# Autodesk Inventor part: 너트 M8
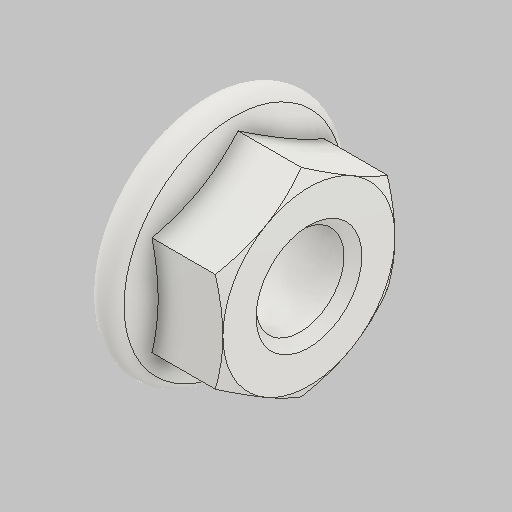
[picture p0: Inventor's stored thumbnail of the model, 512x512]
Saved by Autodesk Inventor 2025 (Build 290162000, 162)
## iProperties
Created: 2024-07
Part Number: 너트 M8
Material: 스테인리스강
Description: 플랜지붙이 6각 너트 - 일반 스레드
Document SubType Name: Modeling
Designer: 현기
Density: 8 g/cm^3
Appearance: 기본값
Author: jhkim
Sending System: Autodesk Inventor 2025
Preprocessor: ST-DEVELOPER v20
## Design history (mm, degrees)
feature "Solid1"
node "솔리드1"
